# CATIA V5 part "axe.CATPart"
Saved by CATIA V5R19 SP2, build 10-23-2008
Part number: axe
Bounding box of the stored display mesh (mm): x 0 to 20, y -2.5 to 2.5, z -2.5 to 2.5
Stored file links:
  U:\IAO\Nouveau dossier\axe.CATPart
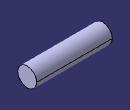
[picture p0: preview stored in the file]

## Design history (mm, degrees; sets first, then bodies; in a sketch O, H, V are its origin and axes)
Body1 (main body)
  Sketch1 on yz-plane, origin (0, 0, 0), H (0, 1, 0), V (0, 0, 1)
    circle A1 centre (0, 0) radius 2.5
    radius A1 = 2.5
  Pad1: profile Sketch1, direction (1, 0, 0), length 20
